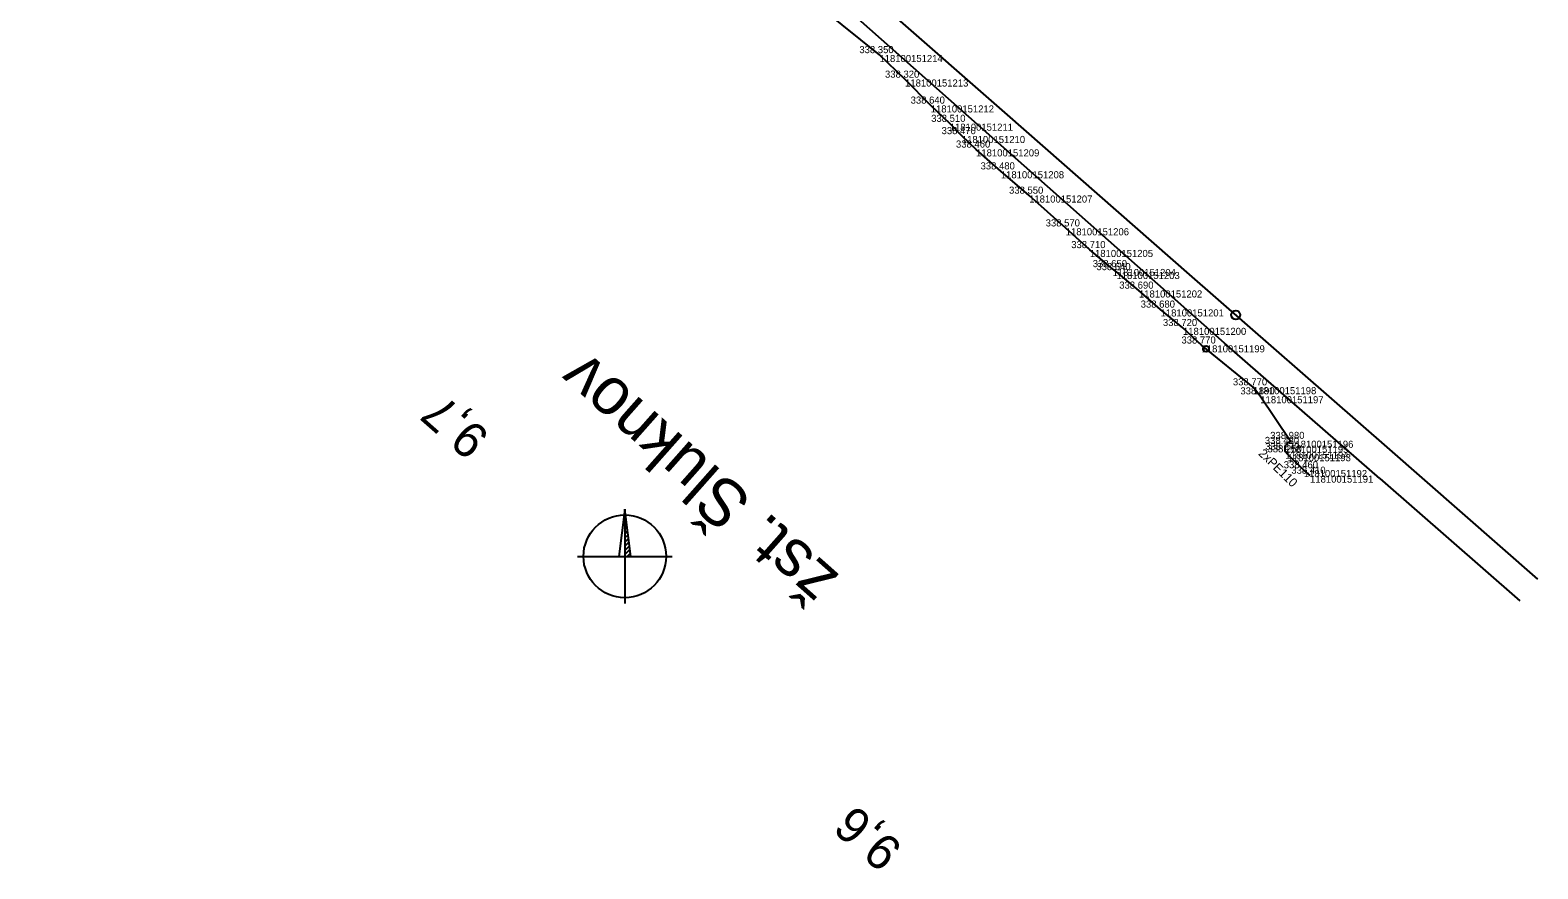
# Model space of a CAD drawing. Extents: x -732194 to -724760, y -944826 to -941477.
# Drawn here: x -726304.2 to -726048.9, y -942196.3 to -942054.3 of the extents above; entities that cross this region are included whole.
import ezdxf

# ---------------------------------------------------------------- set-up
doc = ezdxf.new("R2010")
doc.units = 0
for name, color, linetype in [('Vrstva 1', 7, 'Continuous'), ('Vrstva 23', 7, 'Continuous'), ('Vrstva 28', 7, 'Continuous'), ('Vrstva 31', 7, 'Continuous'), ('Vrstva 35', 7, 'Continuous'), ('Vrstva 36', 7, 'Continuous'), ('Vrstva 50', 7, 'Continuous'), ('Vrstva 60', 7, 'Continuous'), ('Vrstva 61', 7, 'Continuous'), ('Vrstva 7', 7, 'Continuous')]:
    doc.layers.add(name, color=color, linetype=linetype)

msp = doc.modelspace()

# ---------------------------------------------------------------- linework, layer by layer
at = {"layer": 'Vrstva 1'}
msp.add_line((-726075.63, -942130.21), (-726051.95, -942150.89), dxfattribs=at)
for points in [[(-726075.63, -942130.21), (-726101.92, -942107.27), (-726129.96, -942082.52), (-726165.94, -942050.65), (-726201.74, -942019.26), (-726248.07, -941978.65), (-726277.07, -941953.1), (-726291.76, -941938.6), (-726301.83, -941927.65), (-726309.68, -941919.38), (-726318.02, -941911.5), (-726300.8, -941926.68), (-726297.65, -941929.32), (-726289.24, -941936.18), (-726279.87, -941942.93), (-726261.51, -941955.72), (-726252.77, -941962.25), (-726242.17, -941969.3), (-726231.93, -941976.55), (-726224.85, -941981.79)], [(-726048.89, -942147.24), (-726074.43, -942124.89), (-726107.88, -942095.67), (-726138.68, -942068.63), (-726178.07, -942034.11), (-726215.25, -942001.51), (-726245.07, -941975.42), (-726289.24, -941936.18)]]:
    msp.add_lwpolyline(points, dxfattribs=at)
at = {"layer": 'Vrstva 28'}
msp.add_lwpolyline([(-726087.46, -942129.7), (-726088.51, -942128.77), (-726091.26, -942126.08), (-726091.65, -942125.64), (-726091.68, -942124.66), (-726090.83, -942123.81), (-726095.88, -942116.27), (-726097.11, -942114.74), (-726105.82, -942107.66), (-726108.97, -942104.7), (-726112.76, -942101.58), (-726116.42, -942098.37), (-726120.23, -942095.24), (-726120.88, -942094.73), (-726124.75, -942091.51), (-726128.82, -942087.84), (-726135.02, -942082.3), (-726139.81, -942078.19), (-726144, -942074.49), (-726146.41, -942072.22), (-726148.46, -942070.14), (-726151.68, -942067.05), (-726156.02, -942062.66), (-726160.36, -942058.51), (-726179.59, -942042.95)], dxfattribs=at)
at = {"layer": 'Vrstva 31'}
msp.add_lwpolyline([(-726087.46, -942129.7), (-726088.51, -942128.77), (-726091.26, -942126.08), (-726091.65, -942125.64), (-726091.68, -942124.66), (-726090.83, -942123.81), (-726095.88, -942116.27), (-726097.11, -942114.74), (-726105.82, -942107.66), (-726108.97, -942104.7), (-726112.76, -942101.58), (-726116.42, -942098.37), (-726120.23, -942095.24), (-726120.88, -942094.73), (-726124.75, -942091.51), (-726128.82, -942087.84), (-726135.02, -942082.3), (-726139.81, -942078.19), (-726144, -942074.49), (-726146.41, -942072.22), (-726148.46, -942070.14), (-726151.68, -942067.05), (-726156.02, -942062.66), (-726160.36, -942058.51), (-726179.59, -942042.95)], dxfattribs=at)
at = {"layer": 'Vrstva 35'}
msp.add_lwpolyline([(-726088.51, -942128.77), (-726091.26, -942126.08)], dxfattribs=at)
at = {"layer": 'Vrstva 50'}
for p, q in [((-726203.47, -942135.38), (-726203.47, -942151.38)), ((-726203.47, -942136.02), (-726203.39, -942135.95)), ((-726203.47, -942136.72), (-726203.32, -942136.57)), ((-726203.47, -942137.43), (-726203.24, -942137.2)), ((-726203.47, -942138.14), (-726203.16, -942137.83)), ((-726203.47, -942138.84), (-726203.08, -942138.46)), ((-726203.47, -942139.55), (-726203, -942139.09)), ((-726203.47, -942140.26), (-726202.92, -942139.72)), ((-726203.47, -942140.97), (-726202.84, -942140.35)), ((-726203.47, -942141.67), (-726202.77, -942140.97)), ((-726203.47, -942142.38), (-726202.69, -942141.6)), ((-726203.47, -942143.09), (-726202.61, -942142.23)), ((-726203.05, -942143.38), (-726202.53, -942142.86)), ((-726211.47, -942143.38), (-726195.47, -942143.38))]:
    msp.add_line(p, q, dxfattribs=at)
for points in [[(-726203.47, -942135.38), (-726204.47, -942143.38)], [(-726203.47, -942135.38), (-726203.47, -942143.38), (-726202.47, -942143.38), (-726203.47, -942135.38)]]:
    msp.add_lwpolyline(points, dxfattribs=at)
msp.add_circle((-726203.47, -942143.38), 7, dxfattribs=at)
at = {"layer": 'Vrstva 60'}
for p, q in [((-726160.36, -942058.51), (-726160.36, -942058.51)), ((-726156.02, -942062.66), (-726156.02, -942062.66)), ((-726151.68, -942067.05), (-726151.68, -942067.05)), ((-726148.46, -942070.14), (-726148.46, -942070.14)), ((-726146.41, -942072.22), (-726146.41, -942072.22)), ((-726144, -942074.49), (-726144, -942074.49)), ((-726139.81, -942078.19), (-726139.81, -942078.19)), ((-726135.02, -942082.3), (-726135.02, -942082.3)), ((-726128.82, -942087.84), (-726128.82, -942087.84)), ((-726124.75, -942091.51), (-726124.75, -942091.51)), ((-726120.88, -942094.73), (-726120.88, -942094.73)), ((-726120.23, -942095.24), (-726120.23, -942095.24)), ((-726116.42, -942098.37), (-726116.42, -942098.37)), ((-726112.76, -942101.58), (-726112.76, -942101.58)), ((-726108.97, -942104.7), (-726108.97, -942104.7)), ((-726105.82, -942107.66), (-726105.82, -942107.66)), ((-726097.11, -942114.74), (-726097.11, -942114.74)), ((-726095.88, -942116.27), (-726095.88, -942116.27)), ((-726091.68, -942124.66), (-726091.68, -942124.66)), ((-726090.83, -942123.81), (-726090.83, -942123.81)), ((-726091.65, -942125.64), (-726091.65, -942125.64)), ((-726091.26, -942126.08), (-726091.26, -942126.08)), ((-726088.51, -942128.77), (-726088.51, -942128.77)), ((-726087.46, -942129.7), (-726087.46, -942129.7))]:
    msp.add_line(p, q, dxfattribs=at)
at = {"layer": 'Vrstva 7'}
msp.add_line((-726105.11, -942108.24), (-726105.03, -942108.3), dxfattribs=at)
for centre, radius in [((-726100.04, -942102.52), 0.75), ((-726105.07, -942108.27), 0.5)]:
    msp.add_circle(centre, radius, dxfattribs=at)

# ---------------------------------------------------------------- texts
at = {"layer": 'Vrstva 23'}
msp.add_text('žst. Šluknov', height=8, rotation=138.4645, dxfattribs=at).set_placement((-726166.93, -942146.67))
at = {"layer": 'Vrstva 36'}
msp.add_text('2xPE110', height=1.5, rotation=315.6319, dxfattribs=at).set_placement((-726096.3, -942126.1))
at = {"layer": 'Vrstva 60'}
for s, p in [('118100151214', (-726160.36, -942059.71)), ('118100151213', (-726156.02, -942063.86)), ('118100151212', (-726151.68, -942068.25)), ('118100151211', (-726148.46, -942071.34)), ('118100151210', (-726146.41, -942073.42)), ('118100151209', (-726144, -942075.69)), ('118100151208', (-726139.81, -942079.39)), ('118100151207', (-726135.02, -942083.5)), ('118100151206', (-726128.82, -942089.04)), ('118100151205', (-726124.75, -942092.71)), ('118100151204', (-726120.88, -942095.93)), ('118100151203', (-726120.23, -942096.44)), ('118100151202', (-726116.42, -942099.57)), ('118100151201', (-726112.76, -942102.78)), ('118100151200', (-726108.97, -942105.9)), ('118100151199', (-726105.82, -942108.86)), ('118100151198', (-726097.11, -942115.94)), ('118100151197', (-726095.88, -942117.47)), ('118100151195', (-726091.68, -942125.86)), ('118100151196', (-726090.83, -942125.01)), ('118100151194', (-726091.65, -942126.84)), ('118100151193', (-726091.26, -942127.28)), ('118100151192', (-726088.51, -942129.97)), ('118100151191', (-726087.46, -942130.9))]:
    msp.add_text(s, height=1.2, dxfattribs=at).set_placement(p)
at = {"layer": 'Vrstva 61'}
for s, p in [('338.350', (-726163.76, -942058.21)), ('338.320', (-726159.42, -942062.36)), ('338.640', (-726155.08, -942066.75)), ('338.510', (-726151.6, -942069.84)), ('338.470', (-726149.84, -942071.92)), ('338.460', (-726147.4, -942074.19)), ('338.480', (-726143.24, -942077.89)), ('338.550', (-726138.42, -942082)), ('338.570', (-726132.22, -942087.54)), ('338.710', (-726127.89, -942091.21)), ('338.650', (-726124.25, -942094.43)), ('338.640', (-726123.63, -942094.94)), ('338.690', (-726119.76, -942098.07)), ('338.680', (-726116.13, -942101.28)), ('338.720', (-726112.37, -942104.4)), ('338.770', (-726109.23, -942107.36)), ('338.770', (-726100.52, -942114.44)), ('338.890', (-726099.25, -942115.97)), ('338.980', (-726094.2, -942123.51)), ('338.420', (-726095.11, -942124.36)), ('338.270', (-726095.05, -942125.34)), ('338.250', (-726094.66, -942125.78)), ('338.460', (-726091.91, -942128.47)), ('338.410', (-726090.63, -942129.4))]:
    msp.add_text(s, height=1.2, dxfattribs=at).set_placement(p)
at = {"layer": 'Vrstva 7'}
for s, rotation, p in [('9,7', 138.7533, (-726226.08, -942122.84)), ('9,6', 138.8824, (-726156.15, -942192.58))]:
    msp.add_text(s, height=6, rotation=rotation, dxfattribs=at).set_placement(p)

doc.saveas('drawing.dxf')
